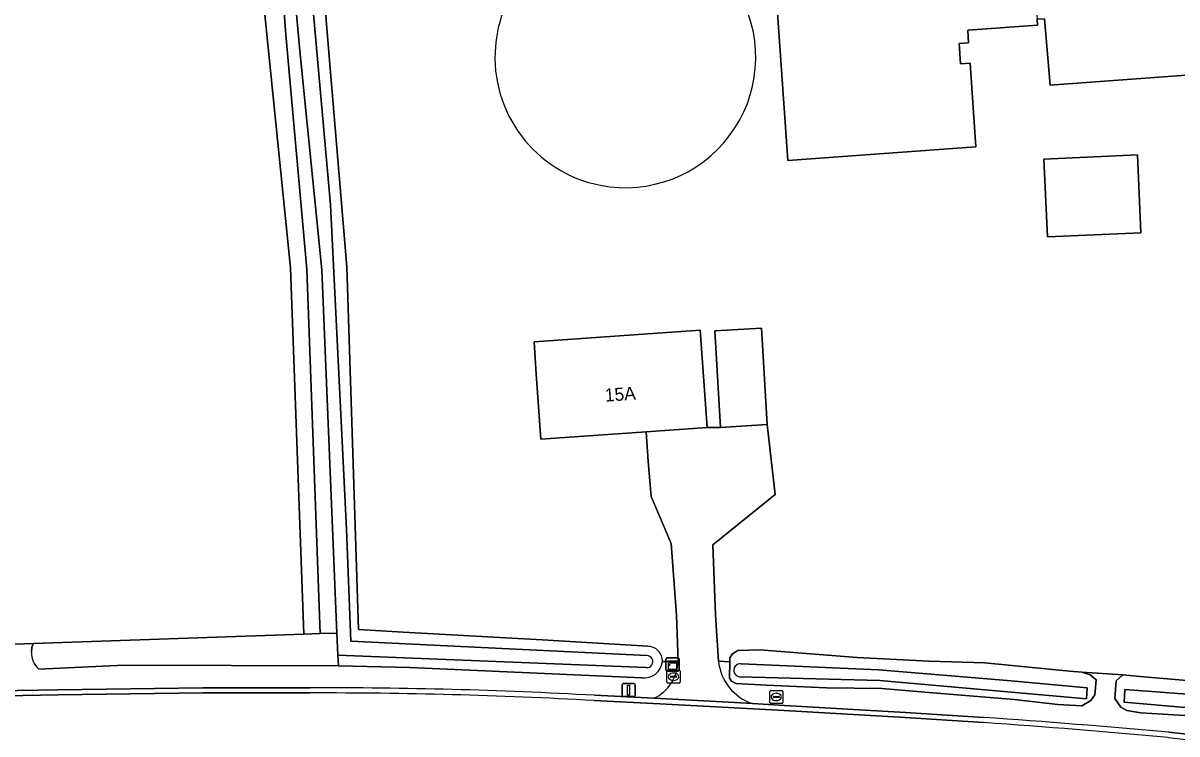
# Model space of a CAD drawing. Extents: x 162510 to 163918, y 388494 to 389774.
# Drawn here: x 162767.9 to 162856.6, y 389045.6 to 389100.2 of the extents above; entities that cross this region are included whole.
import ezdxf

# ---------------------------------------------------------------- set-up
doc = ezdxf.new("R2010")
doc.units = 0
for name, color, linetype in [('IMGEO_Bouwland', 7, 'Continuous'), ('IMGEO_Brandkraan', 7, 'Continuous'), ('IMGEO_Erf', 7, 'Continuous'), ('IMGEO_Grasland_overig', 7, 'Continuous'), ('IMGEO_Groenvoorziening', 7, 'Continuous'), ('IMGEO_Kast', 7, 'Continuous'), ('IMGEO_Lichtmast', 7, 'Continuous'), ('IMGEO_Oever', 7, 'Continuous'), ('IMGEO_Opslagtank', 7, 'Continuous'), ('IMGEO_Pand', 7, 'Continuous'), ('IMGEO_Pand_nummerreeks', 7, 'Continuous'), ('IMGEO_Rijbaan_lokaal_gesloten', 7, 'Continuous'), ('IMGEO_Rijbaan_lokaal_halfverhard', 7, 'Continuous'), ('IMGEO_Rijbaan_lokaal_open', 7, 'Continuous'), ('IMGEO_Rioolput', 7, 'Continuous'), ('IMGEO_Waterloop', 7, 'Continuous')]:
    doc.layers.add(name, color=color, linetype=linetype)

msp = doc.modelspace()

# ---------------------------------------------------------------- linework, layer by layer
at = {"layer": 'IMGEO_Bouwland'}
msp.add_lwpolyline([(162655.166, 389107.621), (162652.745, 389083.952), (162650.857, 389065.794), (162651.566, 389065.632), (162653.989, 389065.078), (162657.8, 389064.433), (162686.069, 389059.649), (162688.964, 389059.201), (162702.649, 389057.082), (162731.841, 389053.7), (162748.803, 389052.862), (162762.9, 389052.38), (162768.724, 389052.581), (162789.49, 389053.299), (162788.462, 389081.4), (162784.276, 389122.828)], dxfattribs=at)
at = {"layer": 'IMGEO_Brandkraan'}
for p, q in [((162825.276, 389048.054), (162825.276, 389048.906)), ((162825.351, 389048.98), (162826.203, 389048.98)), ((162825.535, 389048.474), (162825.535, 389048.486)), ((162825.973, 389048.437), (162825.575, 389048.437)), ((162825.578, 389048.523), (162825.976, 389048.523)), ((162825.787, 389048.2), (162825.762, 389048.2)), ((162825.764, 389048.76), (162825.789, 389048.76)), ((162826.019, 389048.486), (162826.019, 389048.474)), ((162826.277, 389048.906), (162826.277, 389048.054)), ((162826.203, 389047.98), (162825.351, 389047.98))]:
    msp.add_line(p, q, dxfattribs=at)
for points in [[(162825.276, 389048.054), (162825.276, 389048.906)], [(162825.351, 389048.98), (162826.203, 389048.98)], [(162826.277, 389048.906), (162826.277, 389048.054)], [(162826.203, 389047.98), (162825.351, 389047.98)]]:
    msp.add_lwpolyline(points, dxfattribs=at)
for centre, radius, start, end in [((162825.353, 389048.904), 0.0765, 91.55205, 178.44795), ((162825.353, 389048.904), 0.0765, 91.55205, 178.44795), ((162825.575, 389048.483), 0.0403, 85.87752, 175.75265), ((162825.572, 389048.473), 0.0366, 178.93798, 274.71019), ((162825.976, 389048.48), 0.043, 264.86636, 352.45326), ((162825.98, 389048.485), 0.0386, 1.73085, 96.63898), ((162826.201, 389048.904), 0.0765, 1.55205, 88.44795), ((162826.201, 389048.904), 0.0765, 1.55205, 88.44795), ((162825.353, 389048.056), 0.0765, 181.55205, 268.44795), ((162825.353, 389048.056), 0.0765, 181.55205, 268.44795), ((162826.201, 389048.056), 0.0765, 271.55205, 358.44795), ((162826.201, 389048.056), 0.0765, 271.55205, 358.44795)]:
    msp.add_arc(centre, radius, start, end, dxfattribs=at)
for centre, major_axis, ratio, start_param, end_param in [((162825.763, 389048.48), (-0.387, 0.002), 0.722429, 4.712389, 7.853982), ((162825.788, 389048.48), (-0.39, 0.002), 0.717154, 1.570796, 4.712389)]:
    msp.add_ellipse(centre, major_axis=major_axis, ratio=ratio, start_param=start_param, end_param=end_param, dxfattribs=at)
at = {"layer": 'IMGEO_Erf'}
for points in [[(162786.191, 389166.443), (162788.388, 389135.405), (162788.819, 389130.867), (162791.286, 389099.475), (162792.782, 389081.483), (162793.151, 389070.353), (162793.685, 389053.659), (162797.11, 389053.436), (162807.8, 389052.872), (162815.908, 389052.364)], [(162845.82, 389100.504), (162845.854, 389100.033), (162840.486, 389099.641), (162840.556, 389098.68), (162839.818, 389098.627), (162839.926, 389097.05), (162840.664, 389097.102), (162841.115, 389090.691), (162826.655, 389089.653), (162824.122, 389125.824)], [(162868.383, 389097.39), (162868.399, 389097.004), (162846.808, 389095.43), (162846.391, 389100.523)], [(162817.037, 389051.194), (162818.234, 389051.203), (162818.111, 389054.722), (162817.709, 389060.258), (162816.166, 389063.869), (162815.949, 389066.555), (162815.781, 389068.826), (162807.704, 389068.256), (162807.35, 389073.244), (162807.173, 389075.73), (162819.935, 389076.631), (162820.112, 389074.145), (162820.466, 389069.157), (162821.504, 389069.164), (162821.068, 389076.577), (162824.656, 389076.788), (162825.092, 389069.375), (162825.695, 389064.008), (162820.911, 389060.15), (162821.116, 389054.786), (162821.334, 389051.228), (162822.212, 389051.176), (162822.22, 389051.468), (162822.425, 389051.787), (162822.826, 389052.033), (162824.52, 389052.081), (162827.78, 389051.833), (162831.995, 389051.513), (162837.521, 389051.215), (162841.79, 389051.095), (162848.312, 389050.461), (162849.252, 389050.368), (162852.387, 389050.165), (162853.704, 389050.053), (162861.224, 389049.407)]]:
    msp.add_lwpolyline(points, dxfattribs=at)
msp.add_lwpolyline([(162853.524, 389090.079), (162853.792, 389084.096), (162846.61, 389083.774), (162846.342, 389089.757)], close=True, dxfattribs=at)
for centre, radius, start, end in [((162814.19, 389097.571), 10.016, 91.29294, 258.99486), ((162814.189, 389097.571), 10.016, 259.00123, 91.28658), ((162815.897, 389051.223), 1.141, 358.51918, 89.43743)]:
    msp.add_arc(centre, radius, start, end, dxfattribs=at)
at = {"layer": 'IMGEO_Grasland_overig'}
msp.add_lwpolyline([(162790.739, 389053.343), (162789.733, 389081.298), (162788.121, 389099.3), (162786.364, 389122.911), (162784.276, 389122.828), (162788.462, 389081.4), (162789.49, 389053.299)], close=True, dxfattribs=at)
at = {"layer": 'IMGEO_Groenvoorziening'}
for points in [[(162768.569, 389051.925), (162768.608, 389052.298), (162768.724, 389052.581), (162762.9, 389052.38)], [(162815.441, 389049.938), (162797.638, 389050.728), (162792.165, 389050.854), (162775.701, 389050.908), (162769.128, 389050.616)], [(162818.234, 389051.203), (162817.037, 389051.194)], [(162833.882, 389049.133), (162829.627, 389049.185), (162825.027, 389049.37), (162822.692, 389049.517), (162822.343, 389049.692), (162822.179, 389049.907), (162822.212, 389051.176), (162821.334, 389051.228)], [(162857.998, 389046.995), (162853.78, 389047.268), (162852.695, 389047.425), (162852.249, 389047.682), (162851.774, 389048.357), (162851.884, 389049.719), (162852.387, 389050.165), (162849.252, 389050.368), (162849.901, 389050.162), (162850.343, 389049.791), (162850.251, 389048.637), (162849.933, 389048.209), (162849.262, 389047.795), (162847.417, 389047.905), (162844.043, 389048.281), (162837.816, 389048.789), (162833.882, 389049.133)], [(162752, 389048.687), (162759.764, 389048.841), (162770.604, 389049.034), (162781.74, 389049.182), (162789.956, 389049.185)], [(162811.806, 389048.605), (162816.394, 389048.378)], [(162823.956, 389047.963), (162826.412, 389047.828), (162835.708, 389047.296), (162841.73, 389046.903)], [(162855.928, 389045.765), (162859.186, 389045.408), (162859.747, 389045.346)]]:
    msp.add_lwpolyline(points, dxfattribs=at)
for centre, radius, start, end in [((162770.246, 389051.867), 1.678, 178.0357, 228.21348), ((162815.609, 389051.367), 1.439, 263.30547, 353.09771), ((162814.988, 389051.306), 3.248, 295.65695, 358.18844), ((162825.18, 389051.632), 3.867, 185.9892, 251.54411), ((162790.678, 388664.516), 384.669, 86.85141, 90.10751), ((162797.183, 388401.985), 646.455, 84.786197, 86.048638)]:
    msp.add_arc(centre, radius, start, end, dxfattribs=at)
at = {"layer": 'IMGEO_Kast'}
for p, q in [((162817.309, 389050.543), (162817.309, 389051.384)), ((162817.309, 389051.384), (162817.309, 389050.543)), ((162817.384, 389051.468), (162818.225, 389051.468)), ((162818.225, 389051.468), (162817.384, 389051.468)), ((162818.309, 389051.393), (162818.309, 389050.552)), ((162818.309, 389050.552), (162818.309, 389051.393)), ((162818.234, 389050.468), (162817.393, 389050.468)), ((162817.393, 389050.468), (162818.234, 389050.468))]:
    msp.add_line(p, q, dxfattribs=at)
for points in [[(162817.504, 389051.258), (162818.104, 389051.258), (162818.104, 389051.173), (162817.504, 389051.173), (162817.504, 389051.258)], [(162817.504, 389051.083), (162818.104, 389051.083), (162818.104, 389050.594), (162817.504, 389050.594), (162817.504, 389051.083)]]:
    msp.add_lwpolyline(points, dxfattribs=at)
msp.add_circle((162817.588, 389050.932), 0.0377, dxfattribs=at)
for centre, start, end in [((162817.387, 389051.39), 92.4484, 184.28452), ((162817.387, 389051.39), 92.4484, 184.28452), ((162818.231, 389051.39), 2.4484, 94.28452), ((162818.231, 389051.39), 2.4484, 94.28452), ((162817.387, 389050.546), 182.4484, 274.28452), ((162817.387, 389050.546), 182.4484, 274.28452), ((162818.231, 389050.546), 272.4484, 4.28452), ((162818.231, 389050.546), 272.4484, 4.28452)]:
    msp.add_arc(centre, 0.0779, start, end, dxfattribs=at)
at = {"layer": 'IMGEO_Lichtmast'}
for p, q in [((162813.943, 389048.6), (162813.943, 389049.4)), ((162813.943, 389049.4), (162813.943, 389048.6)), ((162814.043, 389049.5), (162814.833, 389049.5)), ((162814.833, 389049.5), (162814.043, 389049.5)), ((162814.933, 389049.4), (162814.933, 389048.6)), ((162814.933, 389048.6), (162814.933, 389049.4)), ((162814.833, 389048.5), (162814.043, 389048.5)), ((162814.043, 389048.5), (162814.833, 389048.5))]:
    msp.add_line(p, q, dxfattribs=at)
msp.add_lwpolyline([(162814.363, 389049.375), (162814.513, 389049.375), (162814.513, 389048.625), (162814.363, 389048.625), (162814.363, 389049.375)], dxfattribs=at)
for centre, start, end in [((162814.043, 389049.4), 90, 180), ((162814.043, 389049.4), 90, 180), ((162814.833, 389049.4), 0, 90), ((162814.833, 389049.4), 360, 90), ((162814.043, 389048.6), 180, 270), ((162814.043, 389048.6), 180, 270), ((162814.833, 389048.6), 270, 0), ((162814.833, 389048.6), 270, 0)]:
    msp.add_arc(centre, 0.1, start, end, dxfattribs=at)
at = {"layer": 'IMGEO_Oever'}
for points in [[(162815.908, 389052.364), (162807.8, 389052.872), (162797.11, 389053.436), (162793.685, 389053.659), (162793.151, 389070.353), (162792.782, 389081.483), (162791.286, 389099.475), (162788.819, 389130.867), (162788.388, 389135.405), (162786.191, 389166.443)], [(162783.396, 389165.633), (162785.763, 389130.994), (162786.364, 389122.911), (162788.121, 389099.3), (162789.733, 389081.298), (162790.739, 389053.343)], [(162790.739, 389053.343), (162792.029, 389053.365), (162790.873, 389081.262), (162789.184, 389098.062), (162788.239, 389108.472), (162783.906, 389165.947)], [(162784.748, 389166.001), (162786.607, 389141.64), (162791.535, 389086.239), (162792.762, 389061.344), (162793.095, 389052.769), (162815.837, 389051.65)], [(162815.785, 389050.741), (162792.099, 389051.676), (162792.165, 389050.854), (162797.638, 389050.728), (162815.441, 389049.938)], [(162823.089, 389051.015), (162833.663, 389050.547), (162843.834, 389049.713), (162849.672, 389049.178), (162849.61, 389048.343), (162833.745, 389049.746), (162822.946, 389050.028)], [(162868.218, 389047.01), (162859.828, 389047.437), (162852.499, 389048.087), (162852.561, 389049.04), (162868.279, 389047.88)]]:
    msp.add_lwpolyline(points, dxfattribs=at)
for points in [[(162822.212, 389051.176), (162822.179, 389049.907), (162822.343, 389049.692), (162822.692, 389049.517), (162825.027, 389049.37), (162829.627, 389049.185), (162833.882, 389049.133), (162837.816, 389048.789), (162844.043, 389048.281), (162847.417, 389047.905), (162849.262, 389047.795), (162849.933, 389048.209), (162850.251, 389048.637), (162850.343, 389049.791), (162849.901, 389050.162), (162849.252, 389050.368), (162848.312, 389050.461), (162841.79, 389051.095), (162837.521, 389051.215), (162831.995, 389051.513), (162827.78, 389051.833), (162824.52, 389052.081), (162822.826, 389052.033), (162822.425, 389051.787), (162822.22, 389051.468)], [(162868.304, 389048.817), (162865.736, 389049.153), (162861.224, 389049.407), (162853.704, 389050.053), (162852.387, 389050.165), (162851.884, 389049.719), (162851.774, 389048.357), (162852.249, 389047.682), (162852.695, 389047.425), (162853.78, 389047.268), (162857.998, 389046.995), (162861.648, 389046.767), (162866.708, 389046.669), (162868.267, 389046.576), (162868.537, 389046.662), (162868.63, 389046.798), (162868.821, 389048.047), (162868.759, 389048.46), (162868.617, 389048.687)]]:
    msp.add_lwpolyline(points, close=True, dxfattribs=at)
for centre, radius, start, end in [((162815.897, 389051.223), 1.141, 358.51918, 89.43743), ((162815.609, 389051.367), 1.439, 263.30547, 353.09771), ((162815.852, 389051.193), 0.457, 261.54176, 91.91008), ((162823.006, 389050.523), 0.499, 80.38603, 263.12627)]:
    msp.add_arc(centre, radius, start, end, dxfattribs=at)
at = {"layer": 'IMGEO_Opslagtank'}
for centre, start, end in [((162814.19, 389097.571), 91.29294, 258.99486), ((162814.189, 389097.571), 259.00123, 91.28658)]:
    msp.add_arc(centre, 10.016, start, end, dxfattribs=at)
at = {"layer": 'IMGEO_Pand'}
msp.add_lwpolyline([(162824.122, 389125.824), (162826.655, 389089.653), (162841.115, 389090.691), (162840.664, 389097.102), (162839.926, 389097.05), (162839.818, 389098.627), (162840.556, 389098.68), (162840.486, 389099.641), (162845.854, 389100.033), (162845.82, 389100.504)], dxfattribs=at)
for points in [[(162853.792, 389084.096), (162853.524, 389090.079), (162846.342, 389089.757), (162846.61, 389083.774)], [(162820.112, 389074.145), (162819.935, 389076.631), (162807.173, 389075.73), (162807.35, 389073.244), (162807.704, 389068.256), (162815.781, 389068.826), (162820.466, 389069.157)], [(162821.068, 389076.577), (162821.504, 389069.164), (162825.092, 389069.375), (162824.656, 389076.788)]]:
    msp.add_lwpolyline(points, close=True, dxfattribs=at)
at = {"layer": 'IMGEO_Rijbaan_lokaal_gesloten'}
for points in [[(162906.835, 389097.483), (162918.812, 389099.65), (162917.437, 389109.243), (162905.069, 389109.103), (162879.88, 389107.285), (162878.058, 389132.496), (162865.123, 389131.64), (162865.544, 389125.247), (162844.91, 389123.873), (162845.512, 389110.547), (162845.089, 389110.527), (162845.82, 389100.504), (162846.391, 389100.523), (162846.808, 389095.43), (162868.399, 389097.004), (162868.383, 389097.39)], [(162789.956, 389048.785), (162781.745, 389048.782), (162770.611, 389048.634), (162759.772, 389048.441), (162752.007, 389048.287)], [(162821.624, 389047.691), (162816.833, 389047.955), (162811.784, 389048.206)], [(162841.704, 389046.504), (162835.685, 389046.897), (162826.39, 389047.429), (162821.624, 389047.691)]]:
    msp.add_lwpolyline(points, dxfattribs=at)
for centre, radius, start, end in [((162790.664, 388663.744), 385.041, 86.85572, 90.10539), ((162796.463, 388392.876), 655.192, 84.795851, 86.040577)]:
    msp.add_arc(centre, radius, start, end, dxfattribs=at)
at = {"layer": 'IMGEO_Rijbaan_lokaal_halfverhard'}
for points in [[(162789.956, 389049.185), (162781.74, 389049.182), (162770.604, 389049.034), (162759.764, 389048.841), (162752, 389048.687)], [(162752.007, 389048.287), (162759.772, 389048.441), (162770.611, 389048.634), (162781.745, 389048.782), (162789.956, 389048.785)], [(162811.784, 389048.206), (162816.833, 389047.955), (162821.624, 389047.691), (162826.39, 389047.429), (162835.685, 389046.897), (162841.704, 389046.504)], [(162841.73, 389046.903), (162835.708, 389047.296), (162826.412, 389047.828), (162823.956, 389047.963), (162821.646, 389048.09), (162816.853, 389048.355), (162816.394, 389048.378), (162811.806, 389048.605)], [(162855.892, 389045.367), (162859.132, 389045.011), (162859.186, 389045.408), (162855.928, 389045.765)]]:
    msp.add_lwpolyline(points, dxfattribs=at)
for centre, radius, start, end in [((162790.678, 388664.516), 384.669, 86.85141, 90.10751), ((162790.664, 388663.744), 385.041, 86.85572, 90.10539), ((162796.463, 388392.876), 655.192, 84.795851, 86.040577), ((162797.183, 388401.985), 646.455, 84.786197, 86.048638)]:
    msp.add_arc(centre, radius, start, end, dxfattribs=at)
at = {"layer": 'IMGEO_Rijbaan_lokaal_open'}
for points in [[(162820.911, 389060.15), (162825.695, 389064.008), (162825.092, 389069.375), (162821.504, 389069.164), (162820.466, 389069.157), (162815.781, 389068.826), (162815.949, 389066.555), (162816.166, 389063.869), (162817.709, 389060.258), (162818.111, 389054.722), (162818.234, 389051.203)], [(162821.334, 389051.228), (162821.116, 389054.786), (162820.911, 389060.15)], [(162816.394, 389048.378), (162816.853, 389048.355), (162821.646, 389048.09), (162823.956, 389047.963)]]:
    msp.add_lwpolyline(points, dxfattribs=at)
for centre, radius, start, end in [((162814.988, 389051.306), 3.248, 295.65695, 358.18844), ((162825.18, 389051.632), 3.867, 185.9892, 251.54411)]:
    msp.add_arc(centre, radius, start, end, dxfattribs=at)
at = {"layer": 'IMGEO_Rioolput'}
for p, q in [((162817.385, 389049.601), (162817.385, 389050.453)), ((162817.46, 389050.527), (162818.312, 389050.527)), ((162817.644, 389050.021), (162817.644, 389050.033)), ((162818.082, 389049.984), (162817.684, 389049.984)), ((162817.687, 389050.07), (162818.085, 389050.07)), ((162817.873, 389050.307), (162817.898, 389050.307)), ((162818.128, 389050.033), (162818.128, 389050.021)), ((162818.386, 389050.453), (162818.386, 389049.601)), ((162818.312, 389049.527), (162817.46, 389049.527)), ((162817.896, 389049.747), (162817.871, 389049.747))]:
    msp.add_line(p, q, dxfattribs=at)
for points in [[(162817.385, 389049.601), (162817.385, 389050.453)], [(162817.46, 389050.527), (162818.312, 389050.527)], [(162818.386, 389050.453), (162818.386, 389049.601)], [(162818.312, 389049.527), (162817.46, 389049.527)]]:
    msp.add_lwpolyline(points, dxfattribs=at)
for centre, radius, start, end in [((162817.462, 389050.451), 0.0765, 91.55205, 178.44795), ((162817.462, 389050.451), 0.0765, 91.55205, 178.44795), ((162817.684, 389050.03), 0.0403, 85.87752, 175.75265), ((162817.681, 389050.02), 0.0366, 178.93798, 274.71019), ((162818.085, 389050.027), 0.043, 264.86636, 352.45326), ((162818.089, 389050.032), 0.0386, 1.73085, 96.63898), ((162818.31, 389050.451), 0.0765, 1.55205, 88.44795), ((162818.31, 389050.451), 0.0765, 1.55205, 88.44795), ((162817.462, 389049.603), 0.0765, 181.55205, 268.44795), ((162817.462, 389049.603), 0.0765, 181.55205, 268.44795), ((162818.31, 389049.603), 0.0765, 271.55205, 358.44795), ((162818.31, 389049.603), 0.0765, 271.55205, 358.44795)]:
    msp.add_arc(centre, radius, start, end, dxfattribs=at)
for centre, major_axis, ratio, start_param, end_param in [((162817.872, 389050.027), (-0.387, 0.002), 0.722429, 4.712389, 7.853982), ((162817.897, 389050.027), (-0.39, 0.002), 0.717154, 1.570796, 4.712389)]:
    msp.add_ellipse(centre, major_axis=major_axis, ratio=ratio, start_param=start_param, end_param=end_param, dxfattribs=at)
at = {"layer": 'IMGEO_Waterloop'}
for points in [[(162783.906, 389165.947), (162788.239, 389108.472), (162789.184, 389098.062), (162790.873, 389081.262), (162792.029, 389053.365), (162792.099, 389051.676), (162815.785, 389050.741)], [(162815.837, 389051.65), (162793.095, 389052.769), (162792.762, 389061.344), (162791.535, 389086.239), (162786.607, 389141.64), (162784.748, 389166.001)], [(162792.029, 389053.365), (162790.739, 389053.343), (162789.49, 389053.299), (162768.724, 389052.581), (162768.608, 389052.298), (162768.569, 389051.925)], [(162769.128, 389050.616), (162775.701, 389050.908), (162792.165, 389050.854), (162792.099, 389051.676), (162792.029, 389053.365)], [(162833.663, 389050.547), (162823.089, 389051.015)], [(162822.946, 389050.028), (162833.745, 389049.746), (162849.61, 389048.343), (162849.672, 389049.178), (162843.834, 389049.713), (162833.663, 389050.547)], [(162852.561, 389049.04), (162852.499, 389048.087), (162859.828, 389047.437), (162868.218, 389047.01)], [(162868.279, 389047.88), (162852.561, 389049.04)]]:
    msp.add_lwpolyline(points, dxfattribs=at)
for centre, radius, start, end in [((162770.246, 389051.867), 1.678, 178.0357, 228.21348), ((162815.852, 389051.193), 0.457, 261.54176, 91.91008), ((162823.006, 389050.523), 0.499, 80.38603, 263.12627)]:
    msp.add_arc(centre, radius, start, end, dxfattribs=at)

# ---------------------------------------------------------------- texts
at = {"layer": 'IMGEO_Pand_nummerreeks'}
msp.add_text('15A', height=1, rotation=4.03935, dxfattribs=at).set_placement((162812.645, 389071.131))

doc.saveas('drawing.dxf')
